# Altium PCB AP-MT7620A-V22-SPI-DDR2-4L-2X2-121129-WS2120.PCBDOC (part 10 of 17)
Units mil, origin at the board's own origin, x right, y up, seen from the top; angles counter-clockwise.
Board outline 7316 x 4279 mil, 4 copper layers (Top, Inner Layer 2, Inner Layer 3, Bottom), stack 35.4 mil thick; 640 components, 473 nets, 2041 pads, 2358 vias.
Unrouted connection lines stored in the file: 11.
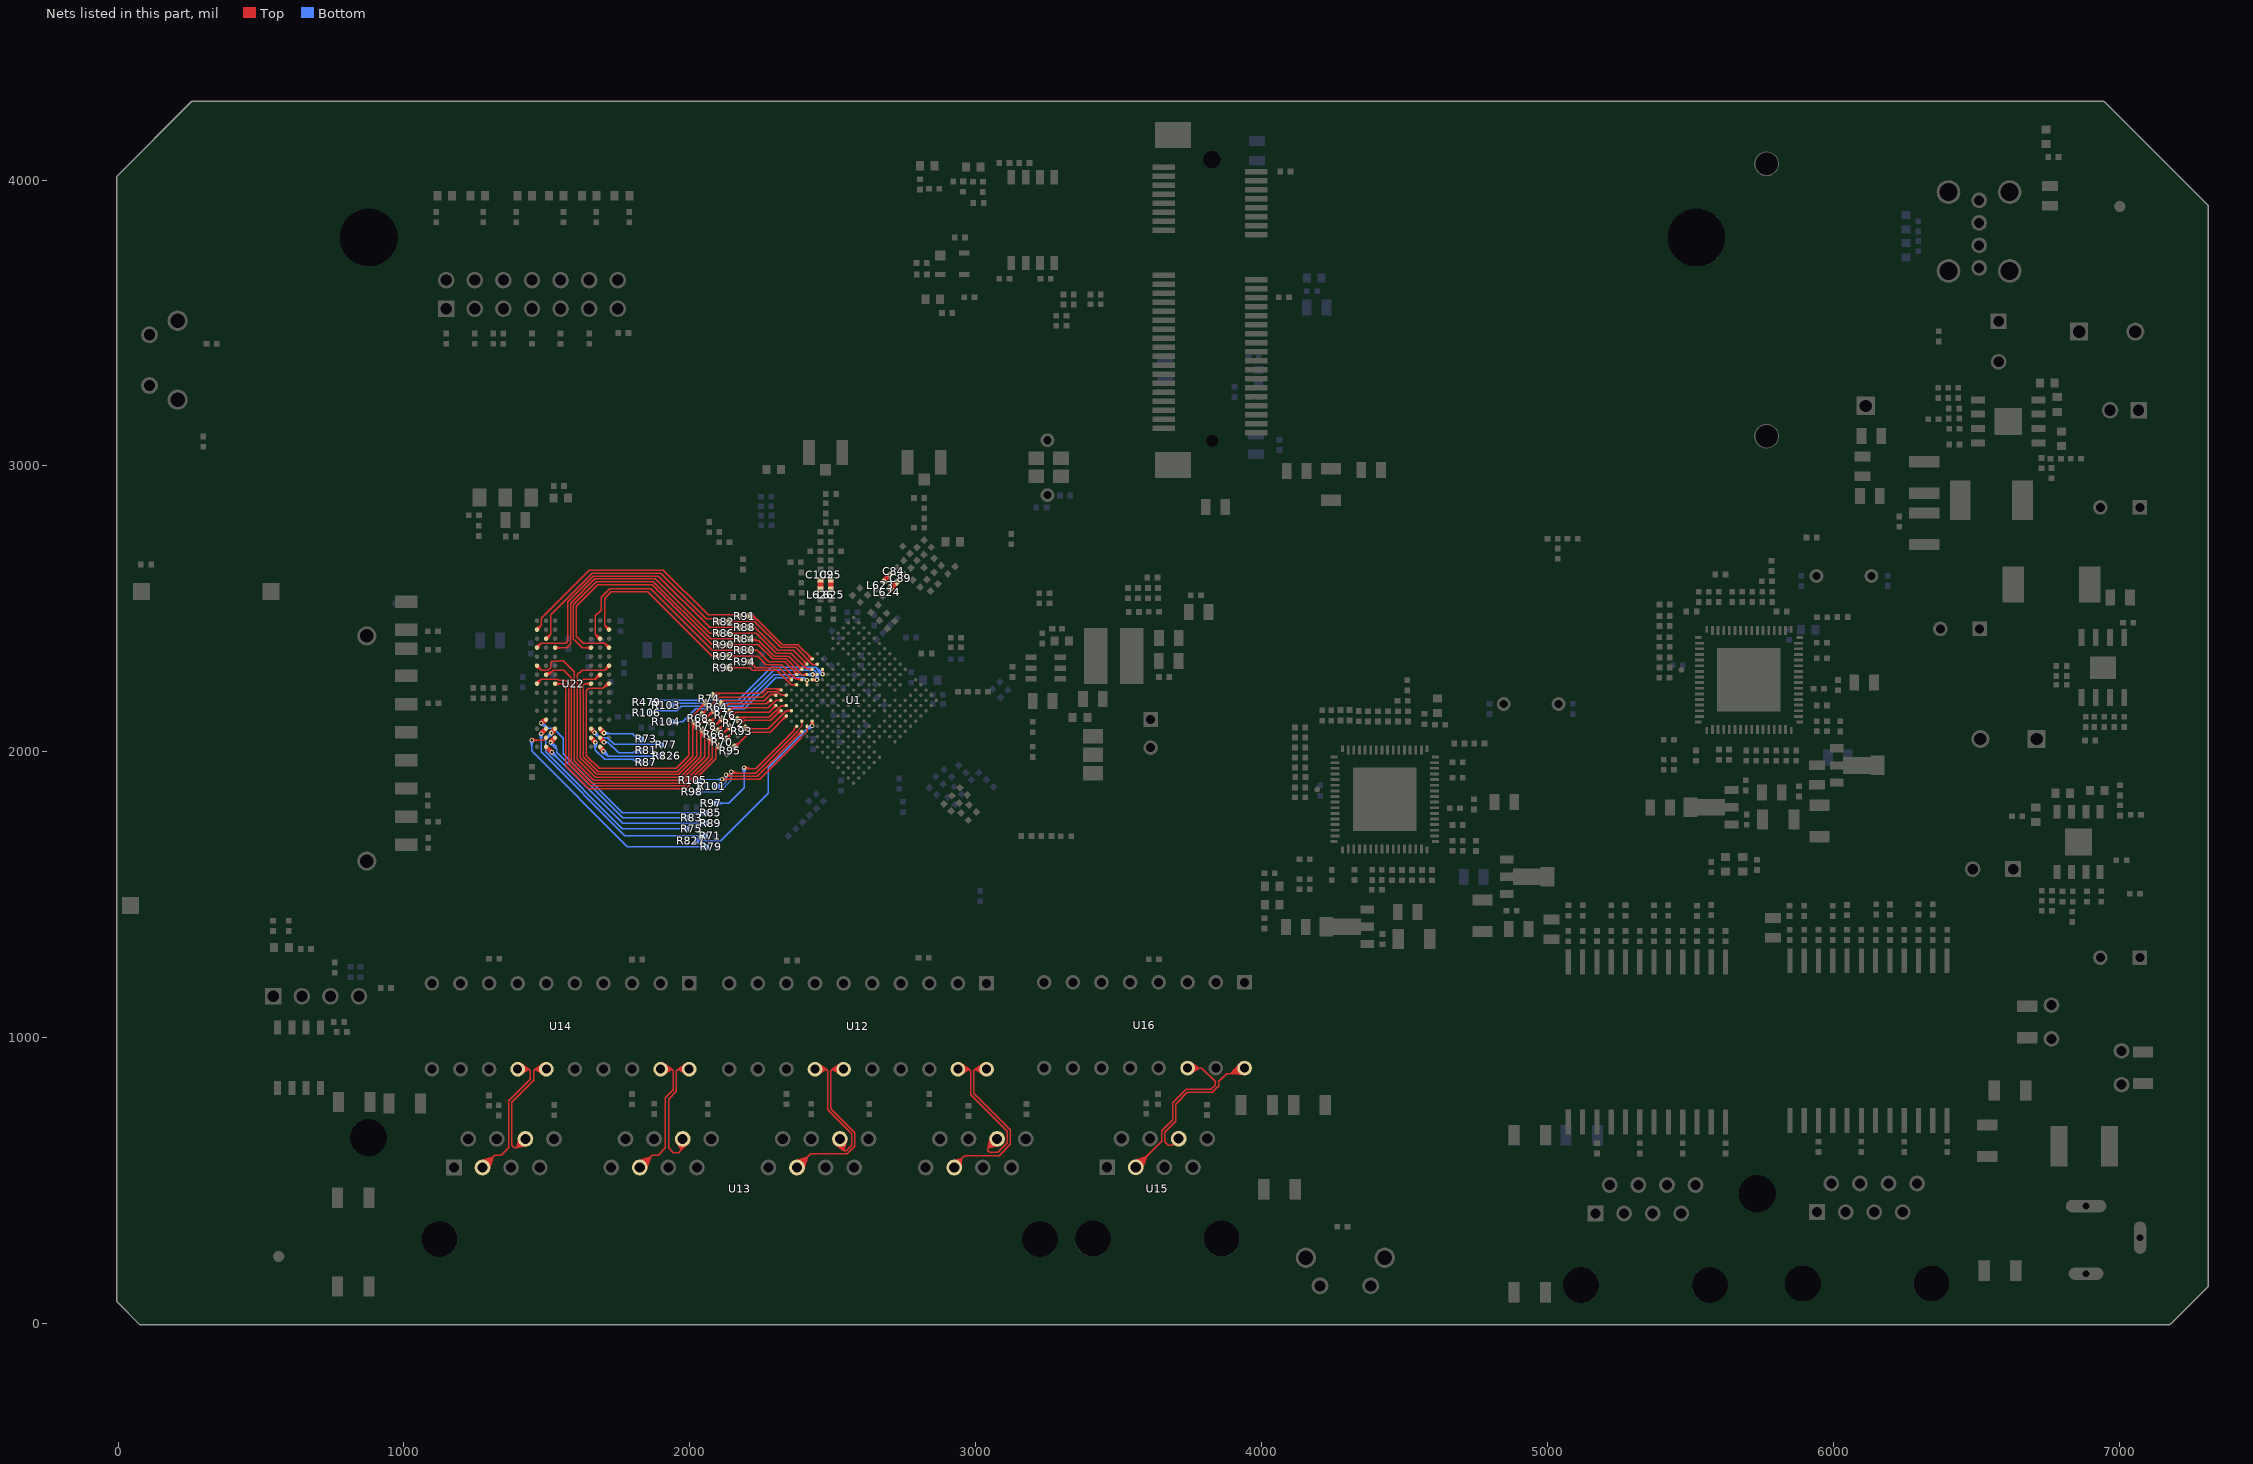
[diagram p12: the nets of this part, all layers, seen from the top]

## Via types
v1: diameter 20, hole 12, Top to Bottom, 2117 vias
v2: diameter 16, hole 8, Top to Bottom, 241 vias

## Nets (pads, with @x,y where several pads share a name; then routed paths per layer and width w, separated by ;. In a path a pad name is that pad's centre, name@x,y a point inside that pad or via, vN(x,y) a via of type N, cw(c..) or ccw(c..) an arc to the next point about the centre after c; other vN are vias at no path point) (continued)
MADDR3: R71.2 U22.N2 | length 1188.1
  Top w4.5: v2@1475.52,2067.6 U22.N2@1492.67,2084.35 ; v2@1477.64,2069.24 U22.N2@1500.52,2076.4 ; v2@1483.54,2059.47 U22.N2@1500.52,2076.4 ; v2@1485.21,2061.57 U22.N2@1492.67,2084.35 ; v2(1480,2064) U22.N2@1497.07,2080.84 ; v2(1480,2064) U22.N2@1500.52,2076.4 ; v2(1480,2064) U22.N2@1492.67,2084.35 ; v2(1480,2064) U22.N2@1497.07,2080.84 ; U22.N2@1497.07,2080.84 1476.48,2068.55 U22.N2@1497.07,2080.84 ; U22.N2@1497.07,2080.84 1484.5,2060.42 U22.N2@1497.07,2080.84
  Bottom w4.5: v2@1474.29,2063.3 1480,2040.5 v2@1485.71,2063.3 ; v2(1480,2064) 1480,2000 1773,1707 R71.2@2054,1707 ; R71.2@2052.72,1699.36 2030.5,1707 ; R71.2@2052.72,1714.64 2030.5,1707 ; R71.2@2053.78,1703.76 2030.5,1707 ; R71.2@2053.78,1710.24 2030.5,1707
MADDR4: R73.2 U22.N8 | length 594.1
  Top w4.5: v2@1694.57,2064.11 U22.N8@1690.68,2084.03 ; v2@1695.3,2062.69 U22.N8@1686.04,2080.84 ; v2@1696.38,2061.53 U22.N8@1682.85,2076.21 ; v2@1702.2,2071.31 U22.N8@1682.85,2076.21 ; v2@1703.59,2070.49 U22.N8@1686.04,2080.84 ; v2@1704.68,2069.34 U22.N8@1690.68,2084.03 ; U22.N8@1682.85,2076.21 v2@1697,2069.88 ; U22.N8@1682.85,2076.21 v2(1700,2066) ; U22.N8@1686.04,2080.84 v2@1697,2069.88 ; U22.N8@1686.04,2080.84 v2(1700,2066) ; U22.N8@1690.68,2084.03 v2@1697,2069.88 ; U22.N8@1690.68,2084.03 v2(1700,2066) ; v2@1697,2069.88 1697,2069 v2(1700,2066)
  Bottom w4.5: v2@1699.85,2060.25 1724.41,2062.5 ; v2@1701.47,2071.56 1724.41,2062.5 ; R73.2@1825.55,2038.65 1804.01,2058.49 ; R73.2@1828.34,2042.2 1804.01,2058.49 ; R73.2@1830,2045 1804.01,2058.49 ; R73.2@1831,2045 1830.5,2045 1829.5,2044 1818.5,2044 1800,2062.5 1705,2062.5 v2(1700,2066) 1724.41,2062.5 ; R73.2@1831.34,2047.96 1804.01,2058.49 ; R73.2@1832.63,2052.29 1804.01,2058.49
MADDR5: R75.2 U22.N3 | length 1113.3
  Top w4.5: v2@1511.13,2069.06 U22.N3@1524.05,2084.19 ; v2@1512.21,2070.32 U22.N3@1528.56,2080.84 ; v2@1513.64,2071.24 U22.N3@1531.91,2076.32 ; v2@1519.82,2061.71 U22.N3@1531.91,2076.32 ; v2@1520.89,2062.97 U22.N3@1528.56,2080.84 ; v2@1521.54,2064.46 U22.N3@1524.05,2084.19 ; v2@1515,2067.28 U22.N3@1528.56,2080.84 ; v2@1515,2067.28 1515,2067 v2(1516,2066) ; v2@1515,2067.28 U22.N3@1531.91,2076.32 ; v2@1515,2067.28 U22.N3@1524.05,2084.19 ; v2(1516,2066) U22.N3@1528.56,2080.84 ; v2(1516,2066) U22.N3@1531.91,2076.32 ; v2(1516,2066) U22.N3@1524.05,2084.19
  Bottom w4.5: v2@1511.3,2069.31 1498.22,2045.72 ; v2@1519.9,2061.77 1498.22,2045.72 ; R75.2@1987.72,1723.36 1965.5,1731 ; R75.2@1987.72,1738.64 1965.5,1731 ; R75.2@1988.78,1727.76 1965.5,1731 ; R75.2@1988.78,1734.24 1965.5,1731 ; R75.2@1989,1731 1965.5,1731 ; R75.2@1990,1731 1764,1731 1495.5,1999.5 1495.5,2043 1516,2063.5 v2(1516,2066) 1498.22,2045.72
MADDR6: R77.2 U22.N7 | length 717
  Top w4.5: v2@1661.47,2065.42 U22.N7@1659.11,2084.13 ; v2@1663.34,2062.57 U22.N7@1651.26,2076.28 ; v2@1669.1,2072.35 U22.N7@1651.26,2076.28 ; v2@1671.79,2070.17 U22.N7@1659.11,2084.13 ; U22.N7@1651.26,2076.28 v2@1667,2068.39 ; U22.N7@1651.26,2076.28 v2(1667,2067) ; U22.N7@1654.55,2080.84 v2@1667,2068.39 ; U22.N7@1654.55,2080.84 v2@1667,2068.39 ; U22.N7@1654.55,2080.84 1662.18,2063.86 U22.N7@1654.55,2080.84 ; U22.N7@1654.55,2080.84 1670.63,2071.46 U22.N7@1654.55,2080.84 ; U22.N7@1654.55,2080.84 v2(1667,2067) ; U22.N7@1654.55,2080.84 v2(1667,2067) ; U22.N7@1659.11,2084.13 v2@1667,2068.39 ; U22.N7@1659.11,2084.13 v2(1667,2067) ; v2(1667,2067) v2@1667,2068.39
  Bottom w4.5: v2@1663.45,2062.48 1684,2050 ; v2(1667,2067) 1684,2050 ; v2@1671.52,2070.55 1684,2050 ; R77.2@1898.09,2017.49 1876.37,2027 ; R77.2@1899.38,2032.73 1876.37,2027 ; R77.2@1899.5,2021.79 1876.37,2027 ; R77.2@1900,2025 1876.37,2027 ; R77.2@1900.05,2028.25 1876.37,2027 ; R77.2@1901,2025 1903,2027 1735,2027 1712,2050 1684,2050
MADDR7: R79.2 U22.P2 | length 1110.7
  Top w4.5: v2@1447.67,2046.71 1470.5,2041.15 ; v2@1447.74,2035.3 1470.5,2041.15 ; U22.P2@1492.31,2052.34 1488.58,2041.15 ; U22.P2@1499.89,2044.48 1488.58,2041.15 ; 1470.5,2041.15 v2(1447,2041) 1447.15,2041.15 1488.58,2041.15 ; 1488.58,2041.15 1496.77,2049.34 U22.P2@1497.07,2049.34 1488.58,2041.15
  Bottom w4.5: v2@1441.29,2040.3 1447,2017.5 v2@1452.71,2040.3 ; v2(1447,2041) 1447,2003 1782,1668 R79.2@2057,1668 2033.5,1668 ; R79.2@2055.72,1660.36 2033.5,1668 ; R79.2@2055.72,1675.64 2033.5,1668 ; R79.2@2056.78,1664.76 2033.5,1668 ; R79.2@2056.78,1671.24 2033.5,1668
MADDR8: R81.2 U22.P8 | length 665
  Top w4.5: v2@1694.56,2032.14 U22.P8@1690.6,2052.64 ; v2@1695.25,2030.76 U22.P8@1686.04,2049.34 ; v2@1695.33,2030.65 U22.P8@1685.7,2049 ; v2@1696.3,2029.6 U22.P8@1682.54,2044.94 ; v2@1702.34,2039.25 U22.P8@1682.54,2044.94 ; v2@1703.57,2038.51 U22.P8@1685.7,2049 ; v2@1703.68,2038.42 U22.P8@1686.04,2049.34 ; v2@1704.73,2037.27 U22.P8@1690.6,2052.64 ; U22.P8@1682.54,2044.94 v2@1700.35,2034.35 ; U22.P8@1682.54,2044.94 v2(1700,2034) ; U22.P8@1685.7,2049 U22.P8@1686.04,2049.34 ; U22.P8@1685.7,2049 v2@1700.35,2034.35 ; U22.P8@1685.7,2049 v2(1700,2034) ; U22.P8@1686.04,2049.34 v2@1700.35,2034.35 ; U22.P8@1686.04,2049.34 v2(1700,2034) ; U22.P8@1690.6,2052.64 v2@1700.35,2034.35 ; U22.P8@1690.6,2052.64 v2(1700,2034) ; v2(1700,2034) v2@1700.35,2034.35
  Bottom w4.5: v2(1700,2034) 1713.57,2034 ; v2@1701.22,2028.38 1713.57,2034 ; v2@1701.22,2039.62 1713.57,2034 ; R81.2@1826.83,2012.07 1800.4,1996 ; R81.2@1828.89,2008.06 1800.4,1996 ; R81.2@1830,2005 1800.4,1996 ; R81.2@1830.78,2001.84 1800.4,1996 ; R81.2@1831,2005 1822,1996 1751.57,1996 1713.57,2034 ; R81.2@1831.31,1997.36 1800.4,1996
MADDR9: R83.2 U22.P3 | length 1011.5
  Top w4.5: v2@1508.38,2036.43 U22.P3@1524.11,2052.78 ; v2@1509.38,2037.46 U22.P3@1528.56,2049.34 ; v2@1510.6,2038.23 U22.P3@1532,2044.89 ; v2@1516.65,2028.56 U22.P3@1532,2044.89 ; v2@1517.64,2029.6 U22.P3@1528.56,2049.34 ; v2@1518.33,2030.84 U22.P3@1524.11,2052.78 ; v2(1513,2033) v2@1513,2033.78 ; v2(1513,2033) U22.P3@1528.56,2049.34 ; v2(1513,2033) U22.P3@1532,2044.89 ; v2(1513,2033) U22.P3@1524.11,2052.78 ; v2@1513,2033.78 U22.P3@1528.56,2049.34 ; v2@1513,2033.78 U22.P3@1532,2044.89 ; v2@1513,2033.78 U22.P3@1524.11,2052.78
  Bottom w4.5: v2@1509.38,2028.53 1532.55,2013.45 v2@1517.47,2036.62 ; v2(1513,2033) 1535,2011 1535,1999 1765,1769 R83.2@1989,1769 ; R83.2@1987.72,1761.36 1965.5,1769 ; R83.2@1987.72,1776.64 1965.5,1769 ; R83.2@1988.78,1765.76 1965.5,1769 ; R83.2@1988.78,1772.24 1965.5,1769
MADDR10: R85.2 U22.M2 | length 1245
  Top w4.5: v2@1476.06,2104.18 U22.M2@1493.55,2116.72 ; v2@1478.77,2105.62 U22.M2@1499.21,2107.13 ; v2@1482.74,2094.94 U22.M2@1499.21,2107.13 ; v2@1484.91,2097.01 U22.M2@1493.55,2116.72 ; v2(1480,2100) v2@1480,2102.27 ; v2(1480,2100) U22.M2@1497.07,2112.33 ; v2(1480,2100) U22.M2@1499.21,2107.13 ; v2(1480,2100) U22.M2@1493.55,2116.72 ; v2(1480,2100) U22.M2@1497.07,2112.33 ; v2@1480,2102.27 U22.M2@1497.07,2112.33 ; v2@1480,2102.27 U22.M2@1499.21,2107.13 ; v2@1480,2102.27 U22.M2@1493.55,2116.72 ; v2@1480,2102.27 U22.M2@1497.07,2112.33 ; U22.M2@1497.07,2112.33 1477.3,2105.08 U22.M2@1497.07,2112.33 ; U22.M2@1497.07,2112.33 1483.97,2095.84 U22.M2@1497.07,2112.33
  Bottom w4.5: v2@1477.33,2094.91 1502.2,2085.1 ; v2@1483.7,2104.4 1502.2,2085.1 ; R85.2@2053.72,1779.36 2031.5,1787 ; R85.2@2053.72,1794.64 2031.5,1787 ; R85.2@2054.78,1783.76 2031.5,1787 ; R85.2@2054.78,1790.24 2031.5,1787 ; R85.2@2055,1787 1763,1787 1557.3,1992.7 1557.3,2047.7 1522.7,2082.3 1505,2082.3 1487.3,2100 v2(1480,2100) 1502.2,2085.1
MADDR11: R87.2 U22.P7 | length 803.9
  Top w4: v2@1664.39,2030.87 U22.P7@1659.26,2052.85 ; v2@1665.13,2029.5 U22.P7@1654.55,2049.34 ; v2@1665.18,2029.43 U22.P7@1654.32,2049.12 ; v2@1666.2,2028.35 U22.P7@1650.91,2044.73 ; v2@1672.43,2038.49 U22.P7@1650.91,2044.73 ; v2@1673.71,2037.72 U22.P7@1654.32,2049.12 ; v2@1673.77,2037.67 U22.P7@1654.55,2049.34 ; v2@1674.85,2036.53 U22.P7@1659.26,2052.85 ; U22.P7@1650.91,2044.73 v2@1670.22,2033.22 ; U22.P7@1650.91,2044.73 v2(1670,2033) ; U22.P7@1654.32,2049.12 U22.P7@1654.55,2049.34 ; U22.P7@1654.32,2049.12 v2@1670.22,2033.22 ; U22.P7@1654.32,2049.12 v2(1670,2033) ; U22.P7@1654.55,2049.34 v2@1670.22,2033.22 ; U22.P7@1654.55,2049.34 v2(1670,2033) ; U22.P7@1659.26,2052.85 v2@1670.22,2033.22 ; U22.P7@1659.26,2052.85 v2(1670,2033) ; v2(1670,2033) v2@1670.22,2033.22
  Bottom w4.5: v2@1664.29,2032.3 1670,2009.5 ; v2@1675.71,2032.3 1670,2009.5 ; R87.2@1826.83,1956.93 1798.23,1974 ; R87.2@1828.87,1960.95 1798.23,1974 ; R87.2@1830.82,1967.14 1798.23,1974 ; R87.2@1831.45,1971.61 1798.23,1974 ; 1670,2009.5 v2(1670,2033) 1670,2006 1702,1974 1821,1974 1831,1964 R87.2@1830,1964 1798.23,1974
MADDR12: R89.2 U22.R2 | length 1180.2
  Top w4.5: U22.R2@1493.72,2013.33 v2@1514.82,2001.18 ; U22.R2@1501.36,2021.47 v2@1514.82,2001.18 ; v2@1511.95,1996.26 U22.R2@1502.3,2020.07 ; v2@1512.52,1995.4 U22.R2@1498.15,2017.85 ; v2@1512.63,1995.26 U22.R2@1497.19,2017.73 ; v2@1513.44,1994.49 U22.R2@1495.52,2012.29 ; v2@1519.45,2004.2 U22.R2@1495.52,2012.29 ; v2@1520.49,2003.57 U22.R2@1497.19,2017.73 ; v2@1520.6,2003.48 U22.R2@1498.15,2017.85 ; v2@1521.32,2002.8 U22.R2@1502.3,2020.07 ; U22.R2@1495.52,2012.29 v2(1517,1999) ; U22.R2@1497.19,2017.73 v2(1517,1999) ; U22.R2@1498.15,2017.85 U22.R2@1497.07,2017.85 v2@1514.82,2001.18 ; U22.R2@1498.15,2017.85 v2(1517,1999) ; U22.R2@1502.3,2020.07 v2(1517,1999)
  Bottom w4.5: v2@1513.38,1994.53 1536.55,1979.45 v2@1521.47,2002.62 ; v2(1517,1999) 1766,1750 R89.2@2056,1750 ; R89.2@2054.72,1742.36 2032.5,1750 ; R89.2@2054.72,1757.64 2032.5,1750 ; R89.2@2055.78,1746.76 2032.5,1750 ; R89.2@2055.78,1753.24 2032.5,1750
MADDR13: R826.2 U22.R8 | length 611.3
  Top w4.5: v2@1692.4,2000.7 U22.R8@1690.63,2021.11 ; v2@1692.96,1999.24 U22.R8@1686.04,2017.85 ; v2@1693.92,1997.95 U22.R8@1682.78,2013.26 ; v2@1700.68,2007.09 U22.R8@1682.78,2013.26 ; v2@1702.04,2006.09 U22.R8@1686.04,2017.85 ; v2@1703.02,2004.8 U22.R8@1690.63,2021.11 ; U22.R8@1682.78,2013.26 v2@1698,2005.89 ; U22.R8@1682.78,2013.26 v2(1698,2002) ; U22.R8@1686.04,2017.85 v2@1698,2005.89 ; U22.R8@1686.04,2017.85 v2(1698,2002) ; U22.R8@1690.63,2021.11 v2@1698,2005.89 ; U22.R8@1690.63,2021.11 v2(1698,2002) ; v2(1698,2002) v2@1698,2005.89
  Bottom w4.5: v2@1694.45,1997.48 1715,1985 ; v2(1698,2002) 1715,1985 ; v2@1702.52,2005.55 1715,1985 ; R826.2@1899.1,1994.51 1877.3,1985 ; R826.2@1900.38,1979.27 1877.3,1985 ; R826.2@1900.51,1990.21 1877.3,1985 ; R826.2@1901,1987 1877.3,1985 ; R826.2@1901.05,1983.75 1877.3,1985 ; R826.2@1902,1987 1900,1985 1715,1985
MB0+_4-ETHERNET: U13.3 U14.14 | length 1397.3
  Top w5: U13.3@1261.88,567.35 1313.17,584.17 ; U13.3@1263.7,562.57 1313.17,584.17 ; U13.3@1265.94,558.03 1313.17,584.17 ; U13.3@1268.58,553.74 1313.17,584.17 ; U13.3@1271.59,549.74 1313.17,584.17 ; U13.3@1275,546 1318.61,589.61 1340.61,589.61 1366.5,615.5 1366.5,779.28 1442.5,855.28 1442.5,884.5 1437,890 ; U13.3@1278.74,542.59 1313.17,584.17 ; U13.3@1282.74,539.58 1313.17,584.17 ; U13.3@1287.03,536.94 1313.17,584.17 ; U13.3@1291.57,534.7 1313.17,584.17 ; U13.3@1296.35,532.88 1313.17,584.17 ; U14.14@1398,890 1437,890 ; U14.14@1398.12,886.91 1437,890 ; U14.14@1398.12,893.09 1437,890 ; U14.14@1398.84,881.95 1437,890 ; U14.14@1398.84,898.05 1437,890 ; U14.14@1400.2,877.1 1437,890 ; U14.14@1400.2,902.9 1437,890 ; U14.14@1402.2,872.4 1437,890 ; U14.14@1402.2,907.6 1437,890 ; U14.14@1404.84,867.94 1437,890 ; U14.14@1404.84,912.06 1437,890
MB0-_4-ETHERNET: U13.6 U14.15 | length 1223.7
  Top w5: U13.6@1402.9,657.81 1394.5,615.5 ; U13.6@1407.91,656.5 1394.5,615.5 ; U13.6@1412.66,654.63 1394.5,615.5 ; U13.6@1417.11,652.23 1394.5,615.5 ; U13.6@1421.22,649.36 1394.5,615.5 ; U13.6@1425,646 1394.5,615.5 ; U13.6@1428.36,642.22 1394.5,615.5 ; U13.6@1431.23,638.11 1394.5,615.5 ; U13.6@1433.63,633.66 1394.5,615.5 ; U13.6@1435.5,628.91 1394.5,615.5 ; U13.6@1436.81,623.9 1394.5,615.5 ; U14.15@1491.16,867.94 1459,890 ; U14.15@1491.16,912.06 1459,890 ; U14.15@1493.8,872.4 1459,890 ; U14.15@1493.8,907.6 1459,890 ; U14.15@1495.8,877.1 1459,890 ; U14.15@1495.8,902.9 1459,890 ; U14.15@1497.16,881.95 1459,890 ; U14.15@1497.16,898.05 1459,890 ; U14.15@1497.88,886.91 1459,890 ; U14.15@1497.88,893.09 1459,890 ; U14.15@1498,890 1459,890 ; 1394.5,615.5 1386,615.5 1377.5,624 1377.5,774.72 1453.5,850.72 1453.5,884.5 1459,890
MB1+_4-ETHERNET: U13.11 U14.19 | length 1375.7
  Top w5: U13.11@1811.88,567.35 1863.17,584.17 ; U13.11@1813.7,562.57 1863.17,584.17 ; U13.11@1815.94,558.03 1863.17,584.17 ; U13.11@1818.58,553.74 1863.17,584.17 ; U13.11@1821.59,549.74 1863.17,584.17 ; U13.11@1825,546 1868.61,589.61 1889.11,589.61 1915,615.5 1915,790.03 1942.5,817.53 1942.5,884.5 1937,890 ; U13.11@1828.74,542.59 1863.17,584.17 ; U13.11@1832.74,539.58 1863.17,584.17 ; U13.11@1837.03,536.94 1863.17,584.17 ; U13.11@1841.57,534.7 1863.17,584.17 ; U13.11@1846.35,532.88 1863.17,584.17 ; U14.19@1898,890 1937,890 ; U14.19@1898.12,886.91 1937,890 ; U14.19@1898.12,893.09 1937,890 ; U14.19@1898.84,881.95 1937,890 ; U14.19@1898.84,898.05 1937,890 ; U14.19@1900.2,877.1 1937,890 ; U14.19@1900.2,902.9 1937,890 ; U14.19@1902.2,872.4 1937,890 ; U14.19@1902.2,907.6 1937,890 ; U14.19@1904.84,867.94 1937,890 ; U14.19@1904.84,912.06 1937,890
MB1-_4-ETHERNET: U13.14 U14.20 | length 1189.6
  Top w5: U13.14@1950.61,640.23 1971,608.5 ; U13.14@1955.21,642.75 1971,608.5 ; U13.14@1960.01,644.58 1971,608.5 ; U13.14@1964.94,645.72 1971,608.5 ; U13.14@1969.94,646.2 1971,608.5 ; U13.14@1975,646 1971,642 1971,608.5 ; U13.14@1979.98,645.13 1971,608.5 ; U13.14@1984.77,643.61 1971,608.5 ; U13.14@1989.35,641.45 1971,608.5 ; U14.20@1991.16,867.94 1959,890 ; U14.20@1991.16,912.06 1959,890 ; U13.14@1993.66,638.64 1971,608.5 ; U14.20@1993.8,872.4 1959,890 ; U14.20@1993.8,907.6 1959,890 ; U14.20@1995.8,877.1 1959,890 ; U14.20@1995.8,902.9 1959,890 ; U14.20@1997.16,881.95 1959,890 ; U14.20@1997.16,898.05 1959,890 ; U13.14@1997.62,635.21 1971,608.5 ; U14.20@1997.88,886.91 1959,890 ; U14.20@1997.88,893.09 1959,890 ; U14.20@1998,890 1959,890 ; 1959,890 1953.5,884.5 1953.5,812.97 1926,785.47 1926,615.5 1943,598.5 1961,598.5 1971,608.5
MB2+_4-ETHERNET: U12.15 U13.19 | length 1509
  Top w5: U13.19@2361.88,567.35 2413.17,584.17 ; U13.19@2363.7,562.57 2413.17,584.17 ; U13.19@2365.94,558.03 2413.17,584.17 ; U13.19@2368.58,553.74 2413.17,584.17 ; U13.19@2371.59,549.74 2413.17,584.17 ; U13.19@2375,546 2422.5,593.5 2551,593.5 2577.5,620 2577.5,668.28 2493.5,752.28 2493.5,884.5 2499,890 ; U13.19@2378.74,542.59 2413.17,584.17 ; U13.19@2382.74,539.58 2413.17,584.17 ; U13.19@2387.03,536.94 2413.17,584.17 ; U13.19@2391.57,534.7 2413.17,584.17 ; U13.19@2396.35,532.88 2413.17,584.17 ; U12.15@2531.16,867.94 2499,890 ; U12.15@2531.16,912.06 2499,890 ; U12.15@2533.8,872.4 2499,890 ; U12.15@2533.8,907.6 2499,890 ; U12.15@2535.8,877.1 2499,890 ; U12.15@2535.8,902.9 2499,890 ; U12.15@2537.16,881.95 2499,890 ; U12.15@2537.16,898.05 2499,890 ; U12.15@2537.88,886.91 2499,890 ; U12.15@2537.88,893.09 2499,890 ; U12.15@2538,890 2499,890
MB2-_4-ETHERNET: U12.14 U13.22 | length 1251.3
  Top w5: U12.14@2438,890 2477,890 ; U12.14@2438.12,886.91 2477,890 ; U12.14@2438.12,893.09 2477,890 ; U12.14@2438.84,881.95 2477,890 ; U12.14@2438.84,898.05 2477,890 ; U12.14@2440.2,877.1 2477,890 ; U12.14@2440.2,902.9 2477,890 ; U12.14@2442.2,872.4 2477,890 ; U12.14@2442.2,907.6 2477,890 ; U12.14@2444.84,867.94 2477,890 ; U12.14@2444.84,912.06 2477,890 ; U13.22@2504.4,631.73 2538.5,604.5 ; U13.22@2507.86,635.58 2538.5,604.5 ; U13.22@2511.7,638.94 2538.5,604.5 ; U13.22@2515.86,641.81 2538.5,604.5 ; U13.22@2520.29,644.16 2538.5,604.5 ; U13.22@2525,646 2525,618 2538.5,604.5 ; U13.22@2529.89,647.28 2538.5,604.5 ; U13.22@2534.86,647.99 2538.5,604.5 ; U13.22@2539.91,648.12 2538.5,604.5 ; U13.22@2544.99,647.66 2538.5,604.5 ; U13.22@2550.05,646.58 2538.5,604.5 ; 2477,890 2482.5,884.5 2482.5,747.72 2566.5,663.72 2566.5,624.56 2546.44,604.5 2538.5,604.5
MB3+_4-ETHERNET: U12.20 U13.27 | length 1401.5
  Top w5: U13.27@2911.34,567.01 2952,578.5 ; U13.27@2913.05,562.11 2952,578.5 ; U13.27@2915.32,557.53 2952,578.5 ; U13.27@2918.08,553.3 2952,578.5 ; U13.27@2921.31,549.46 2952,578.5 ; U13.27@2925,546 2952,578.5 ; U13.27@2929.08,543.01 2952,578.5 ; U13.27@2933.45,540.54 2952,578.5 ; U13.27@2938.11,538.6 2952,578.5 ; U13.27@2943.03,537.21 2952,578.5 ; U13.27@2948.16,536.42 2952,578.5 ; U12.20@3031.16,867.94 2999,890 ; U12.20@3031.16,912.06 2999,890 ; U12.20@3033.8,872.4 2999,890 ; U12.20@3033.8,907.6 2999,890 ; U12.20@3035.8,877.1 2999,890 ; U12.20@3035.8,902.9 2999,890 ; U12.20@3037.16,881.95 2999,890 ; U12.20@3037.16,898.05 2999,890 ; U12.20@3037.88,886.91 2999,890 ; U12.20@3037.88,893.09 2999,890 ; U12.20@3038,890 2999,890 ; 2952,578.5 2961.5,588 3082.14,588 3121.5,627.36 3121.5,677.78 2993.5,805.78 2993.5,884.5 2999,890
MB3-_4-ETHERNET: U12.19 U13.30 | length 1340.6
  Top w5: U12.19@2938,890 2977,890 ; U12.19@2938.12,886.91 2977,890 ; U12.19@2938.12,893.09 2977,890 ; U12.19@2938.84,881.95 2977,890 ; U12.19@2938.84,898.05 2977,890 ; U12.19@2940.2,877.1 2977,890 ; U12.19@2940.2,902.9 2977,890 ; U12.19@2942.2,872.4 2977,890 ; U12.19@2942.2,907.6 2977,890 ; U12.19@2944.84,867.94 2977,890 ; U12.19@2944.84,912.06 2977,890 ; U13.30@3053.12,658.22 3042.5,613.5 ; U13.30@3058.06,656.75 3042.5,613.5 ; U13.30@3062.75,654.76 3042.5,613.5 ; U13.30@3067.15,652.29 3042.5,613.5 ; U13.30@3071.23,649.38 3042.5,613.5 ; U13.30@3075,646 3042.5,613.5 ; U13.30@3078.38,642.23 3042.5,613.5 ; U13.30@3081.29,638.15 3042.5,613.5 ; U13.30@3083.76,633.75 3042.5,613.5 ; U13.30@3085.75,629.06 3042.5,613.5 ; U13.30@3087.22,624.12 3042.5,613.5 ; 2977,890 2982.5,884.5 2982.5,801.22 3110.5,673.22 3110.5,631.92 3077.58,599 3048.5,599 3042.5,605 3042.5,613.5
MB4+_4-ETHERNET: U15.3 U16.14 | length 1527.2
  Top w5: U15.3@3546.88,568.35 3598.17,585.17 ; U15.3@3548.7,563.57 3598.17,585.17 ; U15.3@3550.94,559.03 3598.17,585.17 ; U15.3@3553.58,554.74 3598.17,585.17 ; U15.3@3556.59,550.74 3598.17,585.17 ; U15.3@3560,547 3650.5,637.5 3650.5,674.28 3689,712.78 3689,772.28 3736.22,819.5 3822.9,819.5 3837.42,834.02 3837.42,847.5 3790.92,894 U16.14@3741.3,894 ; U15.3@3563.74,543.59 3598.17,585.17 ; U15.3@3567.74,540.58 3598.17,585.17 ; U15.3@3572.03,537.94 3598.17,585.17 ; U15.3@3576.57,535.7 3598.17,585.17 ; U15.3@3581.35,533.88 3598.17,585.17 ; U16.14@3741.42,890.91 3781.89,894 ; U16.14@3741.42,897.09 3781.89,894 ; U16.14@3742.11,885.95 3781.89,894 ; U16.14@3742.11,902.05 3781.89,894 ; U16.14@3743.41,881.08 3781.89,894 ; U16.14@3743.41,906.92 3781.89,894 ; U16.14@3745.33,876.36 3781.89,894 ; U16.14@3745.33,911.64 3781.89,894 ; U16.14@3747.87,871.86 3781.89,894 ; U16.14@3747.87,916.14 3781.89,894
MB4-_4-ETHERNET: U15.6 U16.16 | length 1031.3
  Top w5: U15.6@3710,647 3686.5,623.5 3673.5,623.5 3661.5,635.5 3661.5,669.5 3700,708 3700,767.72 3740.78,808.5 3827.46,808.5 3850.96,832 3850.96,846.96 3878.14,874.14 3920.53,874.14 U16.16@3940.39,894 ; U16.16@3927.02,912.82 3892.51,874.14 ; U16.16@3930.65,909.24 3892.51,874.14 ; U16.16@3933.89,905.36 3892.51,874.14 ; U16.16@3936.72,901.21 3892.51,874.14 ; U16.16@3939.13,896.82 3892.51,874.14 ; U16.16@3941.49,891.11 3892.51,874.14 ; U16.16@3942.9,886.31 3892.51,874.14 ; U16.16@3943.84,881.37 3892.51,874.14 ; U16.16@3944.27,871.24 3892.51,874.14 ; U16.16@3944.3,876.34 3892.51,874.14
MBA0_1-CPU-RT0: R97.1 U1.U6 | length 694.7
  Top w4.5: v2@2189.51,1939.27 2214.75,1940 ; v2@2191.77,1950.47 2214.75,1940 ; U1.U6@2371.11,2091.83 2365,2081.4 ; U1.U6@2375.97,2086.48 2365,2081.4 ; 2214.75,1940 v2(2190,1945) 2195,1940 2230,1940 2365,2075 2365,2081.4 ; 2365,2081.4 2373.12,2089.52 U1.U6@2373.95,2089.52 2365,2081.4
  Bottom w4.5: R97.1@2093,1821 2137,1821 2190,1874 v2(2190,1945) ; R97.1@2093.22,1817.76 2116.5,1821 ; R97.1@2093.22,1824.24 2116.5,1821 ; R97.1@2094.28,1813.36 2116.5,1821 ; R97.1@2094.28,1828.64 2116.5,1821 ; v2@2184.29,1944.3 2190,1921.5 v2@2195.71,1944.3
MBA1_1-CPU-RT0: R98.1 U1.T6 | length 747.1
  Top w4: 2375.25,2072.25 2392.05,2089.05 ; U1.T6@2388.16,2107.21 2392.05,2089.05 ; U1.T6@2395.93,2107.21 2392.05,2089.05 ; 2392.05,2089.05 U1.T6@2392.05,2107.62 2392.05,2089.05
  Top w4.5: v2@2144.52,1924.27 2170.17,1925 ; v2@2146.75,1935.48 2170.17,1925 ; 2375.25,2072.25 2375.25,2070.25 2230,1925 2150,1925 v2(2145,1930) 2170.17,1925
  Bottom w4: R98.1@2026,1860 2043,1860 ; R98.1@2026.47,1856.03 2043,1860 ; R98.1@2026.47,1863.97 2043,1860 ; R98.1@2027.88,1852.22 2043,1860 ; R98.1@2027.88,1867.78 2043,1860 ; v2@2139.06,1929.18 2145,1908 v2@2150.94,1929.18 ; v2(2145,1930) 2145,1900 2106,1861 2044,1861 2043,1860
MBA2_1-CPU-RT0: R827.1 U1.R7 | length 1002.9
  Top w4.5: v2@2422.25,2090.81 U1.R7@2424.6,2107.27 ; v2@2422.34,2092.01 U1.R7@2428,2107.38 ; v2@2422.35,2092.08 U1.R7@2428.24,2107.62 ; v2@2422.72,2093.28 U1.R7@2431.87,2107.17 ; v2@2433.34,2093.13 U1.R7@2424.6,2107.27 ; v2@2433.66,2092.01 U1.R7@2428,2107.38 ; v2@2433.68,2091.91 U1.R7@2428.24,2107.62 ; v2@2433.74,2090.65 U1.R7@2431.87,2107.17 ; U1.R7@2424.6,2107.27 v2(2428,2091) ; v2(2428,2091) U1.R7@2428,2107.38 ; v2(2428,2091) U1.R7@2431.87,2107.17 ; v2(2428,2091) U1.R7@2428.24,2107.62 ; U1.R7@2428,2107.38 U1.R7@2428.24,2107.62
  Bottom w4.5: R827.1@2024,1689 2109,1689 2275,1855 2275,1945 2421,2091 v2(2428,2091) 2404.38,2074.38 ; R827.1@2024.22,1685.76 2047.5,1689 ; R827.1@2024.22,1692.24 2047.5,1689 ; R827.1@2025.28,1681.36 2047.5,1689 ; R827.1@2025.28,1696.64 2047.5,1689 ; v2@2424.24,2095.35 2404.38,2074.38 ; v2@2430.82,2085.99 2404.38,2074.38
MCAS_N_1-CPU-RT0: R104.1 U1.M3 | length 669.4
  Top w8: v2(2410,2251) U1.M3@2410.14,2234.29 v2@2410.14,2250.86
  Top w10: v2(2410,2251) v2@2410.14,2250.86
  Bottom w4.5: R104.1@1936,2105 1975,2105 2020,2150 2190,2150 2300,2260 2401,2260 v2(2410,2251) ; R104.1@1936.22,2101.76 1959.5,2105 ; R104.1@1936.22,2108.24 1959.5,2105 ; R104.1@1937.28,2097.36 1959.5,2105 ; R104.1@1937.28,2112.64 1959.5,2105
MCKE_1-CPU-RT0: R101.1 U1.U7 | length 638.8
  Top w4.5: v2@2126.51,1914.27 2151.84,1915 ; v2@2128.77,1925.47 2151.84,1915 ; U1.U7@2389.23,2073.76 2378.32,2057.72 ; U1.U7@2394.38,2068.61 2378.32,2057.72 ; 2151.84,1915 v2(2127,1920) 2126,1919 2130,1915 2235.6,1915 U1.U7@2392.05,2071.43 2378.32,2057.72
  Bottom w4: R101.1@2095,1880 2111,1880 ; R101.1@2095.5,1876.03 2111,1880 ; R101.1@2095.5,1883.97 2111,1880 ; R101.1@2097,1872.25 2111,1880 ; R101.1@2097,1887.75 2111,1880 ; v2@2121.06,1919.18 2127,1898 v2@2132.94,1919.18 ; v2(2127,1920) 2127,1896 2111,1880
MCS_N_1-CPU-RT0: R106.1 U1.K3 | length 787.1
  Top w8: v2(2429.5,2270.5) U1.K3@2446.33,2270.48 v2(2429.5,2270.5)
  Bottom w4.5: 1954,2144 1970,2160 2183,2160 2293.5,2270.5 v2(2429.5,2270.5) ; v2@2428.8,2264.79 2406,2270.5 v2@2428.8,2276.21
  Bottom w5: R106.1@1867.15,2144.45 1896.37,2144 ; R106.1@1870.72,2130.01 1896.37,2144 ; 1954,2144 1874,2144 1867,2137 R106.1@1868,2137 1896.37,2144
MD0_1-CPU-RT0: R64.2 U1.T1 | length 318.6
  Top w4.5: R64.2@2105.44,2176.09 2118.93,2179.07 ; R64.2@2107.15,2171.85 2118.93,2179.07 ; R64.2@2109.16,2169.3 2118.93,2179.07 ; R64.2@2111.72,2167.28 2118.93,2179.07 ; R64.2@2115.96,2165.57 2118.93,2179.07 ; U1.T1@2300.63,2194.56 2283,2201.13 ; U1.T1@2301.81,2201.74 2283,2201.13 ; 2118.93,2179.07 2260.93,2179.07 2283,2201.13 ; 2283,2201.13 2298.53,2201.13 U1.T1@2301.57,2198.1 2283,2201.13
MD1_1-CPU-RT0: R66.2 U1.U2 | length 398.3
  Top w4.5: R66.2@2093.92,2080.05 2114.82,2090.82 ; R66.2@2096.37,2076.24 2114.82,2090.82 ; R66.2@2101.05,2071.76 2114.82,2090.82 ; R66.2@2104.96,2069.47 2114.82,2090.82 ; U1.U2@2298.75,2164.23 2287.85,2148.18 U1.U2@2303.9,2159.09 ; U1.U2@2301.57,2161.9 2277.47,2137.8 2161.8,2137.8 2097.85,2073.85 2097.85,2073.13 R66.2@2098.56,2073.84 2114.82,2090.82
MD2_1-CPU-RT0: R68.2 U1.R2 | length 509
  Top w4.5: R68.2@2037.49,2136.71 2058.6,2147.02 ; R68.2@2039.85,2132.86 2058.6,2147.02 ; R68.2@2044.44,2128.27 2058.6,2147.02 ; R68.2@2048.3,2125.9 2058.6,2147.02 ; U1.R2@2337.24,2194.48 2318.8,2199 ; U1.R2@2337.58,2201.75 2318.8,2199 ; 2058.6,2147.02 R68.2@2041.99,2130.41 2102.79,2191.21 2253.21,2191.21 2273,2211 2306.8,2211 2318.8,2199 ; 2318.8,2199 2336.86,2199 U1.R2@2337.76,2198.1 2318.8,2199
MD3_1-CPU-RT0: R70.2 U1.U3 | length 388.7
  Top w4.5: R70.2@2122.34,2051.86 2143.46,2062.17 ; R70.2@2124.71,2048 2143.46,2062.17 ; R70.2@2126.84,2045.55 2192.14,2110.86 2282.86,2110.86 2315.81,2143.81 U1.U3@2319.67,2143.81 2303.45,2131.45 ; R70.2@2129.29,2043.42 2143.46,2062.17 ; R70.2@2133.15,2041.05 2143.46,2062.17 ; U1.U3@2317.2,2146.51 2303.45,2131.45 ; U1.U3@2321.61,2140.72 2303.45,2131.45
MD4_1-CPU-RT0: R72.2 U1.T3 | length 500.9
  Top w4.5: R72.2@2164.56,2120.39 2194.3,2121 ; R72.2@2165,2115.89 2194.3,2121 ; R72.2@2166.8,2109.66 2194.3,2121 ; R72.2@2168.83,2105.63 2194.3,2121 ; U1.T3@2337.39,2158.27 2319.6,2161.9 ; U1.T3@2337.39,2165.54 2319.6,2161.9 ; R72.2@2165.73,2112.73 2174,2121 ; R72.2@2165.73,2112.73 2194.3,2121 ; R72.2@2165.73,2112.73 2174,2121 ; 2174,2121 2278.7,2121 2319.6,2161.9 ; 2174,2121 2162.37,2119.71 2174,2121 ; 2174,2121 2172.71,2109.37 2174,2121 ; 2174,2121 2163.77,2115.32 2174,2121 ; 2174,2121 2168.32,2110.77 2174,2121 ; 2319.6,2161.9 U1.T3@2337.76,2161.9 2319.6,2161.9
MD5_1-CPU-RT0: R74.2 U1.R1 | length 598.6
  Top w4.5: R74.2@2080.01,2205.28 2109.46,2204.7 ; R74.2@2080.27,2200.77 2109.46,2204.7 ; R74.2@2081.84,2194.48 2109.46,2204.7 ; R74.2@2083.73,2190.37 2109.46,2204.7 ; U1.R1@2318.63,2212.68 2297.56,2220.8 ; U1.R1@2320.12,2219.82 2297.56,2220.8 ; R74.2@2080.88,2197.58 2088,2204.7 ; R74.2@2080.88,2197.58 2088,2204.7 ; R74.2@2080.88,2197.58 2109.46,2204.7 ; R74.2@2080.88,2197.58 2088,2204.7 ; 2088,2204.7 2252.2,2204.7 2268.3,2220.8 2315.06,2220.8 ; 2088,2204.7 2077.93,2204.75 2088,2204.7 ; 2088,2204.7 2088.05,2194.63 2088,2204.7 ; 2088,2204.7 2078.98,2200.22 2088,2204.7 ; 2088,2204.7 2083.52,2195.68 2088,2204.7 ; 2297.56,2220.8 U1.R1@2319.67,2216.19 ; 2315.06,2220.8 U1.R1@2319.67,2216.19 ; 2315.06,2220.8 2316.46,2214.43 2315.06,2220.8 ; 2315.06,2220.8 2321.42,2219.4 2315.06,2220.8 ; 2315.06,2220.8 U1.R1@2319.67,2216.19
MD6_1-CPU-RT0: R76.2 U1.T2 | length 339.9
  Top w4.5: R76.2@2133.32,2147.57 2149.83,2153.4 ; R76.2@2135.37,2143.51 2149.83,2153.4 ; R76.2@2139.95,2138.94 2149.83,2153.4 ; R76.2@2144,2136.88 2149.83,2153.4 ; U1.T2@2319.29,2176.36 2301.7,2180 ; U1.T2@2319.29,2183.64 2301.7,2180 ; 2149.83,2153.4 2275.1,2153.4 2301.7,2180 ; 2149.83,2153.4 R76.2@2137.45,2141.01 2149.83,2153.4 ; 2301.7,2180 U1.T2@2319.67,2180 2301.7,2180
MD7_1-CPU-RT0: R78.2 U1.U1 | length 400.3
  Top w4.5: R78.2@2065.77,2108.43 2086.89,2118.74 ; R78.2@2068.14,2104.57 2086.89,2118.74 ; R78.2@2070.27,2102.12 2135.58,2167.42 2267,2167.42 2280.58,2181 2282.48,2181 U1.U1@2283.48,2180 2267.52,2167.94 ; R78.2@2072.72,2099.99 2086.89,2118.74 ; R78.2@2076.58,2097.62 2086.89,2118.74 ; U1.U1@2281.01,2182.7 2267.52,2167.94 ; U1.U1@2285.4,2176.89 2267.52,2167.94
MD8_1-CPU-RT0: R80.2 U1.M1 | length 354.8
  Top w4.5: R80.2@2211,2355 2235.5,2355 2275.5,2315 2333,2315 2373.95,2274.05 U1.M1@2373.95,2270.48 2361.52,2286.48 ; R80.2@2211.22,2351.76 2234.5,2355 ; R80.2@2211.22,2358.24 2234.5,2355 ; R80.2@2212.28,2347.36 2234.5,2355 ; R80.2@2212.28,2362.64 2234.5,2355 ; U1.M1@2370.87,2268.5 2361.52,2286.48 ; U1.M1@2376.63,2272.97 2361.52,2286.48
MD9_1-CPU-RT0: R82.2 U1.J2 | length 516.4
  Top w4.5: R82.2@2136,2455 2228,2455 2318,2365 2370,2365 2430,2305 ; R82.2@2136.22,2451.76 2159.5,2455 ; R82.2@2136.22,2458.24 2159.5,2455 ; R82.2@2137.28,2447.36 2159.5,2455 ; R82.2@2137.28,2462.64 2159.5,2455 ; U1.J2@2445.56,2310.24 2430,2305 ; U1.J2@2446.3,2303.01 2430,2305 ; 2430,2305 2444.67,2305 U1.J2@2446.33,2306.67 2430,2305
MD10_1-CPU-RT0: R84.2 U1.L1 | length 398.5
  Top w4.5: R84.2@2210.05,2387.31 2236.14,2388 ; R84.2@2210.32,2391.82 2236.14,2388 ; R84.2@2212.07,2398.07 2236.14,2388 ; R84.2@2214.16,2402.07 2236.14,2388 ; U1.L1@2389.23,2286.24 2378.33,2302.29 U1.L1@2394.38,2291.39 ; U1.L1@2392.05,2288.57 2345.62,2335 2294.81,2335 2241.81,2388 2215,2388 2215,2395 R84.2@2211,2395 2236.14,2388
MD11_1-CPU-RT0: R86.2 U1.K2 | length 497.7
  Top w4.5: R86.2@2136,2415 2233.3,2415 2303.3,2345 2353.6,2345 2408.6,2290 ; R86.2@2136.22,2411.76 2159.5,2415 ; R86.2@2136.22,2418.24 2159.5,2415 ; R86.2@2137.28,2407.36 2159.5,2415 ; R86.2@2137.28,2422.64 2159.5,2415 ; U1.K2@2427.64,2284.97 2408.6,2290 ; U1.K2@2428.16,2292.23 2408.6,2290 ; 2408.6,2290 2426.81,2290 U1.K2@2428.24,2288.57 2408.6,2290
MD12_1-CPU-RT0: R88.2 U1.K1 | length 378.5
  Top w4.5: R88.2@2211,2435 2228,2435 ; R88.2@2211.31,2431.76 2228,2435 ; R88.2@2211.31,2438.24 2228,2435 ; R88.2@2212.77,2427.45 2228,2435 ; R88.2@2212.77,2442.55 2228,2435 ; U1.K1@2407.33,2304.34 2396.42,2320.39 ; U1.K1@2412.47,2309.48 2396.42,2320.39 ; 2228,2435 2308,2355 2361.81,2355 U1.K1@2410.14,2306.67 2396.42,2320.39
MD13_1-CPU-RT0: R90.2 U1.L2 | length 465.1
  Top w4.5: R90.2@2136,2375 2240.2,2375 2290.2,2325 2337.4,2325 2392.4,2270 ; R90.2@2136.22,2371.76 2159.5,2375 ; R90.2@2136.22,2378.24 2159.5,2375 ; R90.2@2137.28,2367.36 2159.5,2375 ; R90.2@2137.28,2382.64 2159.5,2375 ; U1.L2@2409.67,2274.1 2392.4,2270 ; U1.L2@2409.86,2266.83 2392.4,2270 ; 2392.4,2270 2409.67,2270 U1.L2@2410.14,2270.48 2392.4,2270
MD14_1-CPU-RT0: R91.2 U1.J1 | length 573.6
  Top w4.5: R91.2@2208.26,2467.75 2236.95,2461.05 ; R91.2@2209.62,2472.06 2236.95,2461.05 ; R91.2@2212.69,2477.77 2236.95,2461.05 ; R91.2@2215.54,2481.28 2236.95,2461.05 ; U1.J1@2425.42,2322.43 2414.52,2338.48 U1.J1@2430.57,2327.58 ; U1.J1@2428.24,2324.76 2378,2375 2323,2375 2223,2475 ; R91.2@2211,2475 2223,2475 ; R91.2@2211,2475 2236.95,2461.05 ; R91.2@2211,2475 2223,2475 ; 2223,2475 2213.5,2482.33 2223,2475 ; 2223,2475 2213.5,2467.67 2223,2475 ; 2223,2475 2211.44,2478.22 2223,2475 ; 2223,2475 2211.44,2471.78 2223,2475
MD15_1-CPU-RT0: R92.2 U1.M2 | length 447.3
  Top w4.5: R92.2@2136,2335 2238,2335 2268,2305 2321.2,2305 2371.2,2255 ; R92.2@2136.22,2331.76 2159.5,2335 ; R92.2@2136.22,2338.24 2159.5,2335 ; R92.2@2137.28,2327.36 2159.5,2335 ; R92.2@2137.28,2342.64 2159.5,2335 ; U1.M2@2391.28,2248.81 2371.2,2255 ; U1.M2@2392.19,2256.03 2371.2,2255 ; 2371.2,2255 2389.43,2255 U1.M2@2392.05,2252.38 2371.2,2255
MDATA0: R64.1 U22.G8 | length 1151.9
  Top w4.5: U22.G8@1681.61,2273.27 1669.93,2253.7 ; U22.G8@1686.04,2269.81 1669.93,2253.7 ; U22.G8@1689.5,2265.38 1669.93,2253.7 ; R64.1@2077.4,2148.34 2067.09,2127.22 ; R64.1@2081.26,2145.98 2067.09,2127.22 ; R64.1@2084.41,2144.55 R64.1@2083.71,2143.84 ; R64.1@2085.84,2141.39 2067.09,2127.22 ; R64.1@2088.21,2137.53 2067.09,2127.22 ; 1669.93,2253.7 1626.7,2253.7 1616,2243 1616,1979 1674,1921 1961,1921 2024,1984 2024,2084.13 R64.1@2083.71,2143.84 ; 2067.09,2127.22 R64.1@2083.71,2143.84
MDATA1: R66.1 U22.G2 | length 1396.6
  Top w4.5: U22.G2@1494.96,2275.03 1518.8,2281.61 ; U22.G2@1500.29,2265.21 1518.8,2281.61 ; R66.1@2065.4,2049.28 2066,2020.85 ; R66.1@2069.91,2049.01 2066,2020.85 ; R66.1@2073.81,2049.09 R66.1@2073.1,2048.38 ; R66.1@2076.2,2047.39 2066,2020.85 ; R66.1@2080.27,2045.44 2066,2020.85 ; U22.G2@1497.07,2269.81 1507,2269.81 ; U22.G2@1497.07,2269.81 1518.8,2281.61 ; U22.G2@1497.07,2269.81 1507,2269.81 ; U22.G2@1497.07,2269.81 1507,2269.81 ; 1507,2269.81 1522.69,2285.5 1559.5,2285.5 1586,2259 1586,1964 1659,1891 1976,1891 2066,1981 2066,2041.28 ; 1507,2269.81 1498.66,2275.21 1507,2269.81 ; 1507,2269.81 1498.66,2264.42 1507,2269.81 ; 2066,2020.85 R66.1@2073.1,2048.38 ; 2066,2041.28 R66.1@2073.1,2048.38 ; 2066,2041.28 2076.04,2041.21 2066,2041.28 ; 2066,2041.28 2065.93,2051.32 2066,2041.28 ; 2066,2041.28 2075,2045.74 2066,2041.28 ; 2066,2041.28 2070.46,2050.28 2066,2041.28 ; 2066,2041.28 R66.1@2073.1,2048.38 ; 2066,2041.28 R66.1@2073.1,2048.38
MDATA2: R68.1 U22.H7 | length 1042.8
  Top w4.5: U22.H7@1653.81,2232.74 1633.17,2238.32 ; U22.H7@1653.81,2243.89 1633.17,2238.32 ; R68.1@2008.81,2105.65 2010,2075.92 ; R68.1@2013.33,2105.49 2010,2075.92 ; R68.1@2017.24,2105.66 R68.1@2016.53,2104.95 ; R68.1@2019.66,2104.06 2010,2075.92 ; R68.1@2023.81,2102.28 2010,2075.92 ; 1633.17,2238.32 U22.H7@1654.55,2238.32 1633,2238.32 1627,2232.32 1627,1983 1679,1931 1956,1931 2010,1985 2010,2098.42 R68.1@2016.53,2104.95 ; 2010,2075.92 R68.1@2016.53,2104.95
MDATA3: R70.1 U22.H3 | length 1093.6
  Top w4.5: U22.H3@1528.56,2238.32 1556.68,2238.32 1566,2229 1566,1951 1646,1871 1986,1871 2090,1975 2090,2008.71 ; U22.H3@1529.3,2232.74 1549.94,2238.32 U22.H3@1529.3,2243.89 ; R70.1@2094.75,2024.1 2090,2008.71 ; R70.1@2098.87,2022.15 2090,2008.71 ; R70.1@2102.09,2020.8 R70.1@2101.39,2020.1 ; R70.1@2103.44,2017.58 2090,2008.71 ; R70.1@2105.39,2013.46 2090,2008.71 ; 2090,2008.71 R70.1@2101.39,2020.1 ; 2090,2008.71 R70.1@2101.39,2020.1
MDATA4: R72.1 U22.H1 | length 1295.8
  Top w4.5: U22.H1@1462.15,2242.78 1480.75,2253.5 ; U22.H1@1470.03,2234.9 1480.75,2253.5 ; R72.1@2133.96,2091.77 2123.66,2070.66 ; R72.1@2137.82,2089.41 2123.66,2070.66 ; R72.1@2140.98,2087.98 R72.1@2140.27,2087.27 ; R72.1@2142.41,2084.82 2123.66,2070.66 ; R72.1@2144.77,2080.96 2123.66,2070.66 ; 1480.75,2253.5 U22.H1@1465.57,2238.32 1480.75,2253.5 ; 1480.75,2253.5 1539,2253.5 1541.5,2251 1564,2251 1576,2239 1576,1958 1653,1881 1981,1881 2078,1978 2078,2025 R72.1@2140.27,2087.27 ; 2123.66,2070.66 R72.1@2140.27,2087.27
MDATA5: R74.1 U22.H9 | length 1112.1
  Top w4.5: U22.H9@1713.71,2242.44 1698.16,2224.16 ; U22.H9@1720.3,2233.42 1698.16,2224.16 ; R74.1@2049.11,2176.63 2038.81,2155.51 ; R74.1@2052.97,2174.26 2038.81,2155.51 ; R74.1@2056.13,2172.83 R74.1@2055.42,2172.13 ; R74.1@2057.56,2169.67 2038.81,2155.51 ; R74.1@2059.92,2165.82 2038.81,2155.51 ; 1698.16,2224.16 U22.H9@1717.54,2238.32 1712.32,2238.32 1696,2222 1647,2222 1638,2213 1638,1987 1683,1942 1952,1942 1996,1986 1996,2112.7 R74.1@2055.42,2172.13 ; 2038.81,2155.51 R74.1@2055.42,2172.13
MDATA6: R76.1 U22.F1 | length 1346
  Top w4.5: U22.F1@1462.14,2296.85 1480.88,2286 ; U22.F1@1470.03,2304.74 1480.88,2286 ; R76.1@2105.68,2120.06 2095.37,2098.94 ; R76.1@2109.54,2117.69 2095.37,2098.94 ; R76.1@2112.7,2116.26 R76.1@2111.99,2115.56 ; R76.1@2114.13,2113.11 2095.37,2098.94 ; R76.1@2116.49,2109.25 2095.37,2098.94 ; 1480.88,2286 U22.F1@1465.57,2301.31 1480.88,2286 ; 1480.88,2286 1504,2286 1513,2295 1513,2311 1519,2317 1542.7,2317 1544,2318.3 1557.8,2318.3 1596,2280.1 1596,1969 1664,1901 1971,1901 2052,1982 2052,2055.57 R76.1@2111.99,2115.56 ; 2095.37,2098.94 R76.1@2111.99,2115.56
MDATA7: R78.1 U22.F9 | length 1219.1
  Top w4.5: U22.F9@1713.08,2304.74 1702.23,2286 ; U22.F9@1720.97,2296.85 1702.23,2286 ; R78.1@2037.11,2077.44 2038,2047.7 ; R78.1@2041.62,2077.24 2038,2047.7 ; R78.1@2045.52,2077.37 R78.1@2044.82,2076.67 ; R78.1@2047.93,2075.75 2038,2047.7 ; R78.1@2052.07,2073.92 2038,2047.7 ; 1702.23,2286 1623,2286 1606,2269 1606,1974 1669,1911 1966,1911 2038,1983 2038,2069.85 R78.1@2044.82,2076.67 ; 1702.23,2286 U22.F9@1717.54,2301.31 1702.23,2286 ; 2038,2047.7 R78.1@2044.82,2076.67
MDATA8: R80.1 U22.C8 | length 909.5
  Top w4.5: U22.C8@1681.6,2392.35 1670,2411.84 ; U22.C8@1686.04,2395.8 1670,2411.84 ; U22.C8@1689.5,2400.24 1670,2411.84 ; R80.1@2173.72,2347.36 2151.5,2355 ; R80.1@2173.72,2362.64 2151.5,2355 ; R80.1@2174.78,2351.76 2151.5,2355 ; R80.1@2174.78,2358.24 2151.5,2355 ; R80.1@2176,2355 R80.1@2175,2355 ; 1670,2411.84 1670,2476 1690,2496 1690,2540 1720,2570 1863,2570 2078,2355 R80.1@2175,2355 ; 2151.5,2355 R80.1@2175,2355
MDATA9: R82.1 U22.C2 | length 964.4
  Top w4.5: U22.C2@1493.62,2400.24 1513,2411.73 ; U22.C2@1501.51,2392.35 1513,2411.73 ; R82.1@2094.09,2449.98 2086,2465.5 ; R82.1@2097.82,2452.59 2086,2465.5 ; R82.1@2101,2455 R82.1@2100,2455 ; R82.1@2101.7,2457.77 2086,2465.5 ; R82.1@2103.16,2462.08 2086,2465.5 ; 1513,2411.73 U22.C2@1497.07,2395.8 1513,2411.73 ; 1513,2411.73 1513,2480 1658,2625 1898,2625 2057.5,2465.5 2086,2465.5 ; 2086,2465.5 2096.5,2455 R82.1@2100,2455 ; 2086,2465.5 R82.1@2100,2455
MDATA10: R84.1 U22.D7 | length 1074.9
  Top w4.5: U22.D7@1653.81,2358.73 1633.17,2364.3 ; U22.D7@1653.81,2369.88 1633.17,2364.3 ; R84.1@2173.72,2387.36 2151.5,2395 ; R84.1@2173.72,2402.64 2151.5,2395 ; R84.1@2174.78,2391.76 2151.5,2395 ; R84.1@2174.78,2398.24 2151.5,2395 ; R84.1@2176,2395 R84.1@2175,2395 ; 1633.17,2364.3 U22.D7@1654.55,2364.3 1623.7,2364.3 1593,2395 1593,2515 1673,2595 1873,2595 2073,2395 R84.1@2175,2395 ; 2151.5,2395 R84.1@2175,2395
MDATA11: R86.1 U22.D3 | length 994.7
  Top w4.5: U22.D3@1528.56,2364.3 1570,2364.3 1583,2377.3 1583,2520 1668,2605 1879,2605 2069,2415 R86.1@2100,2415 ; U22.D3@1529.3,2358.73 1549.94,2364.3 U22.D3@1529.3,2369.88 ; R86.1@2098.72,2407.36 2076.5,2415 ; R86.1@2098.72,2422.64 2076.5,2415 ; R86.1@2099.78,2411.76 2076.5,2415 ; R86.1@2099.78,2418.24 2076.5,2415 ; R86.1@2101,2415 R86.1@2100,2415 ; 2076.5,2415 R86.1@2100,2415
MDATA12: R88.1 U22.D1 | length 1153.8
  Top w4.5: U22.D1@1462.13,2368.75 1481.27,2380 ; U22.D1@1470.02,2360.86 1481.27,2380 ; R88.1@2173.72,2427.36 2151.5,2435 ; R88.1@2173.72,2442.64 2151.5,2435 ; R88.1@2174.78,2431.76 2151.5,2435 ; R88.1@2174.78,2438.24 2151.5,2435 ; R88.1@2176,2435 R88.1@2175,2435 ; 1481.27,2380 U22.D1@1465.57,2364.3 1481.27,2380 ; 1481.27,2380 1566,2380 1573,2387 1573,2525 1663,2615 1890,2615 2070,2435 R88.1@2175,2435 ; 2151.5,2435 R88.1@2175,2435
MDATA13: R90.1 U22.D9 | length 1006.8
  Top w4.5: U22.D9@1713.09,2360.86 1701.84,2380 ; U22.D9@1717.54,2364.3 1701.84,2380 ; U22.D9@1720.98,2368.75 1701.84,2380 ; R90.1@2098.63,2367.37 2078,2375 ; R90.1@2098.63,2382.63 2078,2375 ; R90.1@2099.76,2371.76 2078,2375 ; R90.1@2099.76,2378.24 2078,2375 ; R90.1@2101,2375 R90.1@2100,2375 ; 1701.84,2380 1628,2380 1603,2405 1603,2510 1678,2585 1868,2585 2078,2375 ; 2078,2375 R90.1@2100,2375 ; 2078,2375 R90.1@2100,2375
MDATA14: R91.1 U22.B1 | length 1067.6
  Top w4.5: U22.B1@1462.14,2431.75 1481,2442.72 ; U22.B1@1470.03,2423.86 1481,2442.72 ; R91.1@2172.56,2467.64 2150.61,2479 ; R91.1@2174.26,2471.83 2150.61,2479 ; R91.1@2175.04,2482.75 2150.61,2479 ; R91.1@2175.31,2478.24 2150.61,2479 ; 1481,2442.72 U22.B1@1465.57,2427.3 1481,2442.72 ; 1481,2442.72 1481,2468 1648,2635 1908,2635 2064,2479 2172,2479 2176,2475 R91.1@2175,2475 2150.61,2479
MDATA15: R92.1 U22.B9 | length 771.8
  Top w4.5: U22.B9@1713.09,2423.86 1702,2442.83 ; U22.B9@1717.54,2427.3 1702,2442.83 ; U22.B9@1720.97,2431.75 1702,2442.83 ; R92.1@2098.63,2327.37 2078,2335 ; R92.1@2098.63,2342.63 2078,2335 ; R92.1@2099.76,2331.76 2078,2335 ; R92.1@2099.76,2338.24 2078,2335 ; R92.1@2101,2335 R92.1@2100,2335 ; 1702,2442.83 1702,2537 1725,2560 1853,2560 2078,2335 ; 2078,2335 R92.1@2100,2335 ; 2078,2335 R92.1@2100,2335
MDQM0_1-CPU-RT0: R95.1 U1.U4 | length 387.4
  Top w4.5: R95.1@2151.22,2023.96 2173.46,2032.46 ; R95.1@2153.23,2019.91 2173.46,2032.46 ; R95.1@2157.36,2014.91 2173.46,2032.46 ; R95.1@2160.97,2012.19 2173.46,2032.46 ; U1.U4@2334.94,2128.04 2324.04,2111.99 U1.U4@2340.09,2122.9 ; U1.U4@2337.76,2125.71 2281.05,2069 2210,2069 2157.56,2016.56 2154.42,2016.56 R95.1@2155.12,2017.27 2173.46,2032.46
MDQM1_1-CPU-RT0: R96.1 U1.N2 | length 411.8
  Top w4.5: R96.1@2136,2295 2209,2295 2219,2285 2305,2285 2355.71,2234.29 ; R96.1@2136.22,2291.76 2159.5,2295 ; R96.1@2136.22,2298.24 2159.5,2295 ; R96.1@2137.28,2287.36 2159.5,2295 ; R96.1@2137.28,2302.64 2159.5,2295 ; U1.N2@2373.59,2230.65 2355.71,2234.29 ; U1.N2@2373.59,2237.92 2355.71,2234.29 ; 2355.71,2234.29 U1.N2@2373.95,2234.29 2355.71,2234.29
MDQS0_1-CPU-RT0: R93.1 U1.T4 | length 385.4
  Top w4.5: R93.1@2193.69,2081.21 2221.55,2080 ; R93.1@2193.86,2076.7 2221.55,2080 ; R93.1@2194.72,2087.62 2221.55,2080 ; R93.1@2196.3,2091.85 2221.55,2080 ; U1.T4@2355.49,2140.17 2337.71,2143.81 ; U1.T4@2355.49,2147.45 2337.71,2143.81 ; 2221.55,2080 R93.1@2194.02,2084.44 2193.31,2083.74 2197.05,2080 2273.9,2080 2337.71,2143.81 ; 2337.71,2143.81 U1.T4@2355.86,2143.81 2337.71,2143.81
MDQS1_1-CPU-RT0: R94.1 U1.N1 | length 348.1
  Top w4.5: R94.1@2206.19,2308.92 2229.8,2295.2 ; R94.1@2208.78,2312.63 2229.8,2295.2 ; R94.1@2213.49,2317.09 2229.8,2295.2 ; R94.1@2217.32,2319.48 2229.8,2295.2 ; U1.N1@2353.04,2250.05 2342.14,2266.1 U1.N1@2358.19,2255.2 ; U1.N1@2355.86,2252.38 2313.24,2295 2230,2295 2210,2315 R94.1@2211,2315 2229.8,2295.2
MODT_1-CPU-RT0: R479.1 U1.J3 | length 822.6
  Top w8: U1.J3@2464.43,2288.57 v2(2464.5,2272) U1.J3@2464.43,2288.57
  Bottom w4.5: R479.1@1866.61,2181.62 1882,2180.5 ; R479.1@1866.95,2177.08 1882,2180.5 ; R479.1@1869.67,2171.21 1882,2180.5 ; R479.1@1872.92,2168.01 1882,2180.5 ; v2@2460.03,2268.38 2444.95,2291.55 v2@2468.12,2276.47 ; v2(2464.5,2272) 2440.5,2296 2285,2296 2169.5,2180.5 1882,2180.5 ; 1882,2180.5 1875.5,2174 R479.1@1868,2174 1882,2180.5
MRAS_N_1-CPU-RT0: R103.1 U1.L3 | length 925.6
  Top w4.5: v2@2442.63,2257.88 U1.L3@2428.69,2248.75 ; v2@2442.77,2247.26 U1.L3@2428.59,2256.02 ; v2@2443.83,2258.25 U1.L3@2428.24,2252.38 ; v2@2443.91,2246.94 U1.L3@2428.24,2252.6 ; v2@2443.91,2258.26 U1.L3@2428.24,2252.6 ; v2@2443.98,2246.92 U1.L3@2428.24,2252.38 ; v2@2445.09,2258.35 U1.L3@2428.59,2256.02 ; v2@2445.24,2246.86 U1.L3@2428.69,2248.75 ; U1.L3@2428.24,2252.38 U1.L3@2428.24,2252.6 ; U1.L3@2428.24,2252.38 v2(2444.9,2252.6) ; U1.L3@2428.24,2252.6 v2(2444.9,2252.6) ; U1.L3@2428.59,2256.02 v2(2444.9,2252.6) ; U1.L3@2428.69,2248.75 v2(2444.9,2252.6)
  Bottom w4.5: 2020,2170 2177,2170 2293,2286 2435.57,2286 2444.9,2276.67 v2(2444.9,2252.6) ; v2@2439.19,2253.3 2444.9,2276.1 v2@2450.61,2253.3
  Bottom w5: R103.1@1934.15,2170.45 1963.36,2170 ; R103.1@1937.72,2156.01 1963.36,2170 ; 2020,2170 1941,2170 1934,2163 R103.1@1935,2163 1963.36,2170
MWE_N_1-CPU-RT0: R105.1 U1.T7 | length 718.6
  Top w4: 2390,2051 2410.14,2071.14 ; U1.T7@2406.26,2089.11 2410.14,2071.14 ; U1.T7@2410.14,2089.52 2410.14,2071.14 ; U1.T7@2414.03,2089.11 2410.14,2071.14
  Top w4.5: v2(2113,1904) 2244,1904 2390,2050 2390,2051 ; v2@2113.7,1898.29 2136.5,1904 v2@2113.7,1909.71
  Bottom w4: R105.1@2027.65,1903.98 2050.55,1904 ; R105.1@2028,1908 2050.55,1904 ; R105.1@2029.04,1896.14 2050.55,1904 ; R105.1@2030.75,1892.49 2050.55,1904 ; v2@2112.18,1898.06 2091,1904 v2@2112.18,1909.94 ; v2(2113,1904) 2027,1904 2027,1900 R105.1@2028,1900 2050.55,1904
O_N_1-CPU-RT0: C89.1 L624.2 | length 544
  Top w8: C89.1@2719.46,2597.4 L624.2@2705.71,2566.34 ; C89.1@2720.05,2598.28 L624.2@2701.05,2570.12 ; C89.1@2720.11,2598.35 L624.2@2700.69,2570.48 ; C89.1@2720.79,2599.04 L624.2@2697.13,2574.66 ; C89.1@2727.77,2589.33 L624.2@2697.13,2574.66 ; C89.1@2728.56,2589.89 L624.2@2700.69,2570.48 ; C89.1@2728.63,2589.95 L624.2@2701.05,2570.12 ; C89.1@2729.37,2590.71 L624.2@2705.71,2566.34 ; L624.2@2697.13,2574.66 C89.1@2724.71,2594.49 ; L624.2@2697.13,2574.66 C89.1@2724.71,2594.49 ; L624.2@2700.69,2570.48 C89.1@2724.71,2594.49 ; L624.2@2700.69,2570.48 L624.2@2701.05,2570.12 ; L624.2@2700.69,2570.48 C89.1@2724.71,2594.49 ; L624.2@2701.05,2570.12 C89.1@2724.71,2594.49 ; L624.2@2701.05,2570.12 C89.1@2724.71,2594.49 ; L624.2@2705.71,2566.34 C89.1@2724.71,2594.49 ; L624.2@2705.71,2566.34 C89.1@2724.71,2594.49
O_N_1_1-CPU-RT0: C102.1 L626.2 | length 340
  Top w8: C102.1@2451.02,2601.47 L626.2@2457,2568 ; C102.1@2451.02,2602.53 L626.2@2451.02,2568.53 ; C102.1@2451.21,2600.43 L626.2@2462.98,2568.53 ; C102.1@2462.79,2600.43 L626.2@2451.02,2568.53 ; C102.1@2462.98,2601.47 L626.2@2457,2568 ; C102.1@2462.98,2602.53 L626.2@2462.98,2568.53 ; L626.2@2451.02,2568.53 C102.1@2457,2602 ; L626.2@2457,2568 C102.1@2457,2602 ; L626.2@2457,2568 C102.1@2457,2602 ; C102.1@2457,2602 L626.2@2462.98,2568.53
O_P_1-CPU-RT0: C84.1 L623.2 | length 519.1
  Top w8: C84.1@2694.53,2621.79 L623.2@2683.6,2591.37 ; C84.1@2695.09,2622.75 L623.2@2678.73,2594.87 ; C84.1@2695.34,2623.07 L623.2@2677.16,2596.44 ; C84.1@2695.82,2623.59 L623.2@2674.59,2599.21 ; C84.1@2703.23,2614.21 L623.2@2674.59,2599.21 ; C84.1@2703.79,2614.62 L623.2@2677.16,2596.44 ; C84.1@2704.1,2614.9 L623.2@2678.73,2594.87 ; C84.1@2704.83,2615.74 L623.2@2683.6,2591.37 ; L623.2@2674.59,2599.21 C84.1@2699.96,2619.24 ; L623.2@2674.59,2599.21 C84.1@2699.96,2619.24 ; L623.2@2677.16,2596.44 C84.1@2699.96,2619.24 ; L623.2@2677.16,2596.44 L623.2@2678.73,2594.87 ; L623.2@2677.16,2596.44 C84.1@2699.96,2619.24 ; L623.2@2678.73,2594.87 C84.1@2699.96,2619.24 ; L623.2@2678.73,2594.87 C84.1@2699.96,2619.24 ; L623.2@2683.6,2591.37 C84.1@2699.96,2619.24 ; L623.2@2683.6,2591.37 C84.1@2699.96,2619.24
O_P_1_1-CPU-RT0: C95.1 L625.2 | length 374
  Top w8: C95.1@2487.02,2601.47 L625.2@2493,2568 ; C95.1@2487.02,2602.53 L625.2@2487.02,2568.53 ; C95.1@2487.21,2600.43 L625.2@2498.98,2568.53 ; C95.1@2498.79,2600.43 L625.2@2487.02,2568.53 ; C95.1@2498.98,2601.47 L625.2@2493,2568 ; C95.1@2498.98,2602.53 L625.2@2498.98,2568.53 ; L625.2@2487.02,2568.53 C95.1@2493,2602 ; L625.2@2487.02,2568.53 C95.1@2493,2602 ; L625.2@2493,2568 C95.1@2493,2602 ; L625.2@2493,2568 C95.1@2493,2602 ; C95.1@2493,2602 L625.2@2498.98,2568.53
